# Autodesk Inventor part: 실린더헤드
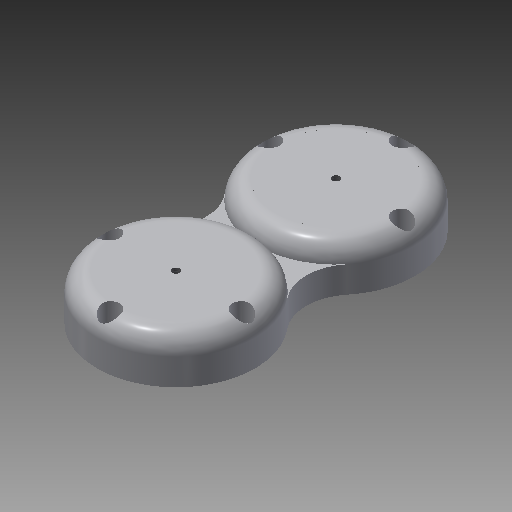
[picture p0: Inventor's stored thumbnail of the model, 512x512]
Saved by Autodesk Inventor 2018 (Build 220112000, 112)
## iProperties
Created: 2016-11
Part Number: 실린더헤드
Material: 알루미늄 6061
Document SubType Name: Modeling
Designer: mduedu
Density: 2.71 g/cm^3
Mass: 538.465 g
Surface Area: 423.673 cm^2
Volume: 198.695 cm^3
Appearance: 알루미늄 - 평지
Author: mduedu
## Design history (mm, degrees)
sketch "스케치1"
  geometry: C1 r 42 at (0, 0); 1 further point
  constraints: 1 centre point, 1 coincident
  dimensions: "d0" = 84 diameter of C1
extrude "돌출1" new body sketch "스케치1" distance "d1" = 24; taper "d2" = 0 deg
fillet "모깎기1" dims "d3" = 10
sketch "스케치2"
  geometry: C1 r 30 at (0, 0); 1 further point
  constraints: 1 centre point, 1 coincident
  dimensions: "d4" = 60 diameter of C1
extrude "돌출2" join sketch "스케치2" distance "d5" = 5; taper "d6" = 0 deg
sketch "스케치3"
  geometry: C1 r 25 at (0, 0); 1 further point
  constraints: 1 centre point, 1 coincident
  dimensions: "d7" = 50 diameter of C1
extrude "돌출3" cut sketch "스케치3" distance "d8" = 20; taper "d9" = 0 deg
hole "구멍1" diameter "d12" = 4.134; stored, may be unused: countersink angle "d16" = 90 deg, drill point angle "d18" = 118 deg; dims "d10" = 10, "d11" = 10, "d13" = 6, "d14" = 4, "d15" = 2, "d17" = 8
chamfer "모따기1" distance "d19" = 1; stored, may be unused: second distance "d20" = 2, angle "d21" = 45 deg
fillet "모깎기2" dims "d22" = 3
sketch "스케치4"
  geometry: C1 r 17.5 at (0, 0); 1 further point
  constraints: 1 centre point, 1 coincident
  dimensions: "d23" = 35 diameter of C1
extrude "돌출4" cut sketch "스케치4" distance "d24" = 2; taper "d25" = 0 deg
fillet "모깎기3" dims "d26" = 0.5
sketch "스케치5" dims "d32" = 70
  geometry: C1 r 5 at (0, 35); 3 further points
  constraints: 2 coincident, 2 vertical alignment, 1 centre point, 2 other
  dimensions: "d33" = 10 diameter of C1
extrude "돌출5" cut sketch "스케치5" distance "d34" = 10; taper "d35" = 0 deg
sketch "스케치6"
  geometry: A1 r 35 centre (0, -35) between (0, 0) and (-35, -35); 2 further points
  constraints: 3 point on circle, 2 horizontal alignment, 1 centre point, 1 coincident, 1 vertical alignment
  dimensions: "d39" = 70 diameter of A1
hole "구멍3" sketch "스케치6" at (0, 0), (-35, -35), (35, -35) diameter "d57" = 5.5; stored, may be unused: countersink angle "d61" = 90 deg, drill point angle "d63" = 118 deg; dims "d58" = 6, "d59" = 4, "d60" = 2, "d62" = 8
chamfer "모따기2" distance "d54" = 5; stored, may be unused: second distance "d55" = 2, angle "d56" = 30 deg
node "작업 평면1"
sketch "스케치8"
  geometry: L1 (0, 85)-(0, 0); A1 r 42 centre (0, 85) between (-32.469, 58.358) and (32.469, 58.358) reference; A2 r 42 centre (0, 0) between (-32.469, 26.642) and (32.469, 26.642) reference; A3 r 25 centre (51.795, 42.5) between (32.469, 26.642) and (32.469, 58.358); A4 r 25 centre (-51.795, 42.5) between (-32.469, 58.358) and (-32.469, 26.642); A5 r 25 centre (-51.795, 42.5) between (-32.469, 26.642) and (-32.469, 58.358); A6 r 25 centre (51.795, 42.5) between (32.469, 58.358) and (32.469, 26.642); A7 r 42 centre (0, 85) between (-32.469, 58.358) and (32.469, 58.358); A8 r 42 centre (0, 0) between (32.469, 26.642) and (-32.469, 26.642); 1 further point
  constraints: 16 point on circle, 6 centre point, 2 coincident, 2 end point, 2 tangent, 1 symmetric about line, 1 vertical, 1 other
  dimensions: "d65" = 50 diameter of A3
extrude "돌출6" join sketch "스케치8" distance "d67" = 14; taper "d68" = 0 deg
node "솔리드1"
pattern_circular "원형 패턴1" dims angle "d37" = 360 deg
mirror "대칭1"
other parameters: "d64" = 42.5
